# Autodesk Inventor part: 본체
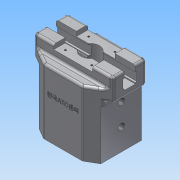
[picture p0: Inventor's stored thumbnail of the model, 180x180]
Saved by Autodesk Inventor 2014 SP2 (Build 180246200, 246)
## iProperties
Created: 2023-05
Part Number: 본체
Material: 알루미늄 6061
Document SubType Name: Modeling
Designer: 거성
Density: 2.71 g/cm^3
Appearance: 알루미늄 - 평지
Mass: 927.998 g
Surface Area: 564.044 cm^2
Volume: 342.435 cm^3
Author: 거성
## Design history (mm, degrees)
sketch "스케치1"
  geometry: L1 (40, -35)-(-40, -35); L2 (-40, -35)-(-40, 35); L3 (-40, 35)-(40, 35); L4 (40, 35)-(40, -35); L5 (40, -35)-(-40, 35); L6 (-40, -35)-(40, 35); 1 further point
  constraints: 12 end point, 2 midpoint, 2 parallel, 1 horizontal, 1 perpendicular
  dimensions: "d9" = 80 distance of L2.end L3.end; "d10" = 70 distance of L1.end L2.end
extrude "돌출1" new body sketch "스케치1" stored distance "d11" = 70; taper "d12" = 0 deg
sketch "스케치4"
  geometry: L1 (-35, -35)-(-35, 35) reference; L2 (-35, 35)-(35, 35) reference; L3 (35, 35)-(35, -35) reference; L4 (35, -35)-(-35, -35) reference; L5 (35, 35)-(35, -35); L6 (35, -35)-(49, -35); L7 (49, -35)-(49, -22); L8 (49, -22)-(64, -22); L9 (64, -22)-(64, 22); L10 (64, 22)-(49, 22); L11 (49, 22)-(49, 35); L12 (49, 35)-(35, 35); 1 further point
  constraints: 16 end point, 4 parallel, 2 collinear, 2 equal length, 2 perpendicular
  dimensions: "d25" = 29 distance between parallel lines of L5 L9; "d26" = 44 distance of L8.end L9.end; "d27" = 15 distance of L7.end L8.end
extrude "돌출3" join sketch "스케치4" stored distance "d28" = 102; taper "d29" = 0 deg
sketch "스케치5"
  geometry: L1 (102, 44)-(102, 0) reference; L2 (0, -13)-(102, -13) reference; L3 (102, 0)-(102, -13) reference; L4 (0, 0)-(102, 0) reference; L5 (0, -13)-(0, 0) reference; L6 (0, 57)-(102, 57) reference; L7 (0, 44)-(102, 44) reference; L8 (102, 57)-(102, 44) reference; L9 (0, 57)-(102, 57) reference; L10 (0, 44)-(0, 57) reference; L11 (76.019, 57)-(102, 42); L12 (102, 2)-(76.019, -13); L13 (76.019, 57)-(102, 57); L14 (102, 57)-(102, 42); L15 (102, 2)-(102, -13); L16 (102, -13)-(76.019, -13); 1 further point
  constraints: 12 end point, 4 collinear, 4 point on line, 1 equal length
  dimensions: "d30" = 30 deg angle of L2 L11; "d31" = 30 deg angle of L6 L12; "d32" = 40 distance of L12.start L11.end
  node "투영된 루프1"
  node "투영된 루프2"
extrude "돌출4" cut sketch "스케치5" distance "d33" = 102; taper "d34" = 0 deg
sketch "스케치6"
  geometry: L1 (20, 64)-(-20, 64) reference; L2 (-20, 64)-(20, 64) reference; L3 (20, 64)-(20, 35) reference; L4 (20, 35)-(-20, 35) reference; L5 (-20, 35)-(-20, 64) reference; L6 (-7.2, 44.518)-(-9, 45); L7 (-9, 45)-(-9, 56); L8 (-9, 56)-(-7.2, 56.482); L9 (-7.2, 56.482)-(-7.2, 64); L10 (-7.2, 64)-(7.2, 64); L11 (7.2, 64)-(7.2, 56.482); L12 (7.2, 56.482)-(9, 56); L13 (9, 56)-(9, 45); L14 (9, 45)-(7.2, 44.518); L15 (-20, 35)-(20, 35) reference; L16 (-7.2, 44.518)-(-7.2, 43); L17 (-7.2, 43)-(7.2, 43); L18 (7.2, 43)-(7.2, 44.518); 5 further points
  constraints: 24 end point, 4 midpoint, 4 perpendicular, 3 equal length, 3 parallel, 2 point on line, 1 coincident, 1 vertical alignment
  dimensions: "d36" = 18 distance between parallel lines of L13 L7; "d37" = 8 vertical distance of L10.end L12.end; "d38" = 11 distance of L12.end L13.end; "d39" = 30 deg angle of L14 L12; "d40" = 14.4 distance between parallel lines of L11 L9; "d45" = 8 vertical distance of L7.end L9.end; "d47" = 30 deg angle of L6 L8; "d80" = 21 distance between parallel lines of L17 L1; "d81" = 1.51769 distance of L17.end L14.end
extrude "돌출5" cut sketch "스케치6" distance "d48" = 102; taper "d49" = 0 deg
sketch "스케치7"
  geometry: L1 (40, 35)-(40, -35) reference; L2 (40, -35)-(-40, -35) reference; L3 (-40, -35)-(-40, 35) reference; L4 (40, 35)-(40, -35) reference; L5 (40, -35)-(-40, -35) reference; L6 (-40, -35)-(-40, 35) reference; L7 (51, 64)-(51, 56.482) reference; L8 (-51, 64)-(51, 64) reference; L9 (-51, 56.482)-(-51, 64) reference; L10 (51, 56.482)-(-51, 56.482) reference; L11 (51, 56)-(51, 45) reference; L12 (51, 56)-(-51, 56) reference; L13 (-51, 45)-(-51, 56) reference; L14 (51, 45)-(-51, 45) reference; L15 (51, 44.518)-(51, 35) reference; L16 (51, 44.518)-(-51, 44.518) reference; L17 (-51, 35)-(-51, 44.518) reference; L18 (-40, 35)-(-51, 35) reference; L19 (40, 35)-(-40, 35) reference; L20 (51, 35)-(40, 35) reference; L21 (0, 64)-(0, -35); L22 (12, 64)-(12, 34); L23 (12, 34)-(8, 34); L24 (8, 34)-(8, 30.6); L25 (8, 30.6)-(10, 30.6); L26 (10, 30.6)-(10, 27.4); L27 (10, 27.4)-(8, 27.4); L28 (8, 27.4)-(8, 24); L29 (8, 24)-(25, 24); L30 (25, 24)-(25, -21); L31 (25, -21)-(30, -21); L32 (30, -21)-(30, -27); L33 (30, -27)-(31.5, -27); L34 (31.5, -27)-(31.5, -29.2); L35 (31.5, -29.2)-(30, -29.2); L36 (30, -29.2)-(30, -35); L37 (-51, 43)-(51, 43) reference; L38 (51, 43)-(51, 35) reference; L39 (51, 35)-(40, 35) reference; L40 (-40, 35)-(-51, 35) reference; L41 (-51, 35)-(-51, 43) reference; L42 (-51, 43)-(51, 43) reference; L43 (51, 43)-(51, 35) reference; L44 (51, 35)-(40, 35) reference; L45 (-40, 35)-(-51, 35) reference; L46 (-51, 35)-(-51, 43) reference; 1 further point
  constraints: 32 end point, 8 perpendicular, 7 parallel, 2 midpoint, 2 point on line
  dimensions: "d50" = 24 diameter of L22 L21; "d51" = 16 diameter of L24 L21; "d52" = 20 diameter of L26 L21; "d53" = 16 diameter of L28 L21; "d54" = 50 diameter of L30 L21; "d55" = 60 diameter of L32 L21; "d56" = 63 diameter of L34 L21; "d57" = 60 diameter of L36 L21; "d58" = 30 distance of L22.start L22.end; "d59" = 45 distance of L29.end L30.end; "d60" = 14 distance between parallel lines of L2 L31; "d61" = 2.2 distance of L33.end L34.end; "d62" = 6 distance of L31.end L32.end; "d63" = 3.2 distance of L25.end L26.end; "d65" = 3.4 distance of L23.end L24.end
revolve "회전1" sketch "스케치7" stored, may be unused: angle "d66" = 90 deg
sketch "스케치8"
  geometry: L1 (-95.072, 15)-(0, 15) reference; L2 (-72.536, 15)-(-22.536, 15); L3 (-22.536, 15)-(-22.536, 9); L4 (-22.536, 9)-(-72.536, 9); L5 (-72.536, 9)-(-72.536, 15); L6 (-72.536, 15)-(-22.536, 9); L7 (-22.536, 15)-(-72.536, 9); 3 further points
  constraints: 12 end point, 4 midpoint, 2 parallel, 1 horizontal, 1 perpendicular
  dimensions: "d67" = 50 distance of L3.end L4.end; "d68" = 6 distance of L2.end L3.end
extrude "돌출6" cut sketch "스케치8" stored distance "d69" = 102; taper "d70" = 0 deg
sketch "스케치9"
  geometry: L1 (0, 0)-(0, 70) reference; L2 (-52.702, 70)-(0, 70) reference; L3 (-33.551, 70)-(-19.151, 70) reference; L4 (-52.702, 70)-(0, 70) reference; L5 (-52.702, 70)-(-52.702, 0) reference; L6 (0, 0)-(-52.702, 0) reference; L7 (-52.702, 64)-(-52.702, 70); L8 (-52.702, 70)-(0, 70); L9 (0, 70)-(0, 64); L10 (0, 64)-(-52.702, 64); 1 further point
  constraints: 8 end point, 2 perpendicular, 2 point on line, 1 collinear
  dimensions: "d71" = 64 distance between parallel lines of L6 L10
extrude "돌출7" join sketch "스케치9" distance "d72" = 2; taper "d73" = 0 deg
extrude "돌출8" cut sketch "스케치5" stored distance "d74" = 2; taper "d75" = 0 deg
sketch "스케치10"
  geometry: L1 (15.4, -14.8)-(0, -14.8) reference; L2 (-4, -22)-(54, -22); L3 (-4, -28)-(54, -28); L4 (54, -16)-(-4, -16); A1 r 12 centre (25, -22) between (34.6, -14.8) and (15.4, -14.8) reference; A2 r 6 centre (-4, -22) between (-4, -16) and (-4, -28); A3 r 6 centre (54, -22) between (54, -28) and (54, -16)
  constraints: 8 end point, 4 point on circle, 4 tangent, 2 centre point, 2 parallel, 1 midpoint
  dimensions: "d76" = 12 distance between parallel lines of L3 L4; "d77" = 58 distance of L2.end L2.start
extrude "돌출9" cut sketch "스케치10" distance "d78" = 24; taper "d79" = 0 deg
sketch "스케치12"
  geometry: A1 r 12 centre (25, -22) between (34.6, -14.8) and (15.4, -14.8) reference; 1 further point
  dimensions: "d83" = 15 vertical distance of A1.centre point (8, -7); "d84" = 17 horizontal distance of A1.centre point (8, -7)
hole "구멍1" sketch "스케치12" at (8, -7) diameter "d85" = 2.459; stored, may be unused: countersink angle "d89" = 90 deg, drill point angle "d91" = 118 deg; dims "d86" = 6, "d87" = 4, "d88" = 2, "d90" = 8
sketch "스케치13"
  geometry: C1 r 30 at (0, 0) reference; 1 further point
  dimensions: "d92" = 26 horizontal distance of point (26, -25) C1.centre; "d93" = 25 vertical distance of C1.centre point (26, -25)
hole "구멍2" sketch "스케치13" at (26, -25) diameter "d94" = 4.917; stored, may be unused: countersink angle "d98" = 90 deg, drill point angle "d100" = 118 deg; dims "d95" = 12, "d96" = 4, "d97" = 2, "d99" = 14
sketch "스케치14"
  geometry: L1 (52.702, 0)-(0, 0) reference; 3 further points
  constraints: 2 vertical alignment
  dimensions: "d101" = 28 distance from line of L1 point (26.351, 28); "d102" = 28 distance of point (26.351, 28) point (26.351, 56)
hole "구멍3" sketch "스케치14" diameter "d103" = 4; stored, may be unused: countersink angle "d107" = 90 deg, drill point angle "d109" = 0 deg; dims "d104" = 12, "d105" = 4, "d106" = 2, "d108" = 14
hole "구멍4" sketch "스케치14" diameter "d110" = 8; stored, may be unused: countersink angle "d116" = 90 deg, drill point angle "d118" = 118 deg; dims "d111" = 9, "d112" = 0.62479, "d113" = 7.985, "d114" = 4, "d115" = 2, "d117" = 11
fillet "모깎기2" dims "d119" = 3
fillet "모깎기3" dims "d120" = 3
fillet "모깎기4" dims "d121" = 3
fillet "모깎기5" dims "d122" = 3
fillet "모깎기6" dims "d123" = 3
fillet "모깎기7" dims "d124" = 3
fillet "모깎기8" dims "d125" = 3
fillet "모깎기9" dims "d126" = 3
fillet "모깎기10" dims "d127" = 3
fillet "모깎기11" dims "d128" = 0.4
chamfer "모따기1" distance "d129" = 1; stored, may be unused: second distance "d130" = 2, angle "d131" = 45 deg
chamfer "모따기2" distance "d132" = 2; stored, may be unused: second distance "d133" = 2, angle "d134" = 20 deg
fillet "모깎기12" dims "d135" = 2
sketch "스케치15"
  geometry: L1 (49.215, 93)-(-0.785, 93) reference; L2 (-15.785, 67.804)-(-15.785, 0) reference; 2 further points
  constraints: 1 other
  dimensions: "d136" = 40 distance from line of L2 point (24.215, 53); "d137" = 40 distance from line of point (24.215, 53) L1
feature "엠보싱1" sketch "스케치15" dims "d138" = 0.5, "d139" = 0
node "솔리드1"
mirror "대칭2"
mirror "대칭3"
mirror "대칭4"
mirror "대칭5"
mirror "대칭6"
node "투영된 루프3"
node "투영된 루프4"
node "투영된 루프5"
node "절단 모서리 투영1"
node "절단 모서리 투영2"
node "절단 모서리 투영3"
node "절단 모서리 투영4"
